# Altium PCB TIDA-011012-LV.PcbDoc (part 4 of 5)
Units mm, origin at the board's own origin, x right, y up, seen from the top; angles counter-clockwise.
Board outline 250 x 280 mm, 4 copper layers (Top Layer, Layer 1, Layer 2, Bottom Layer), stack 2.208 mm thick; 410 components, 230 nets, 1280 pads, 1868 vias.
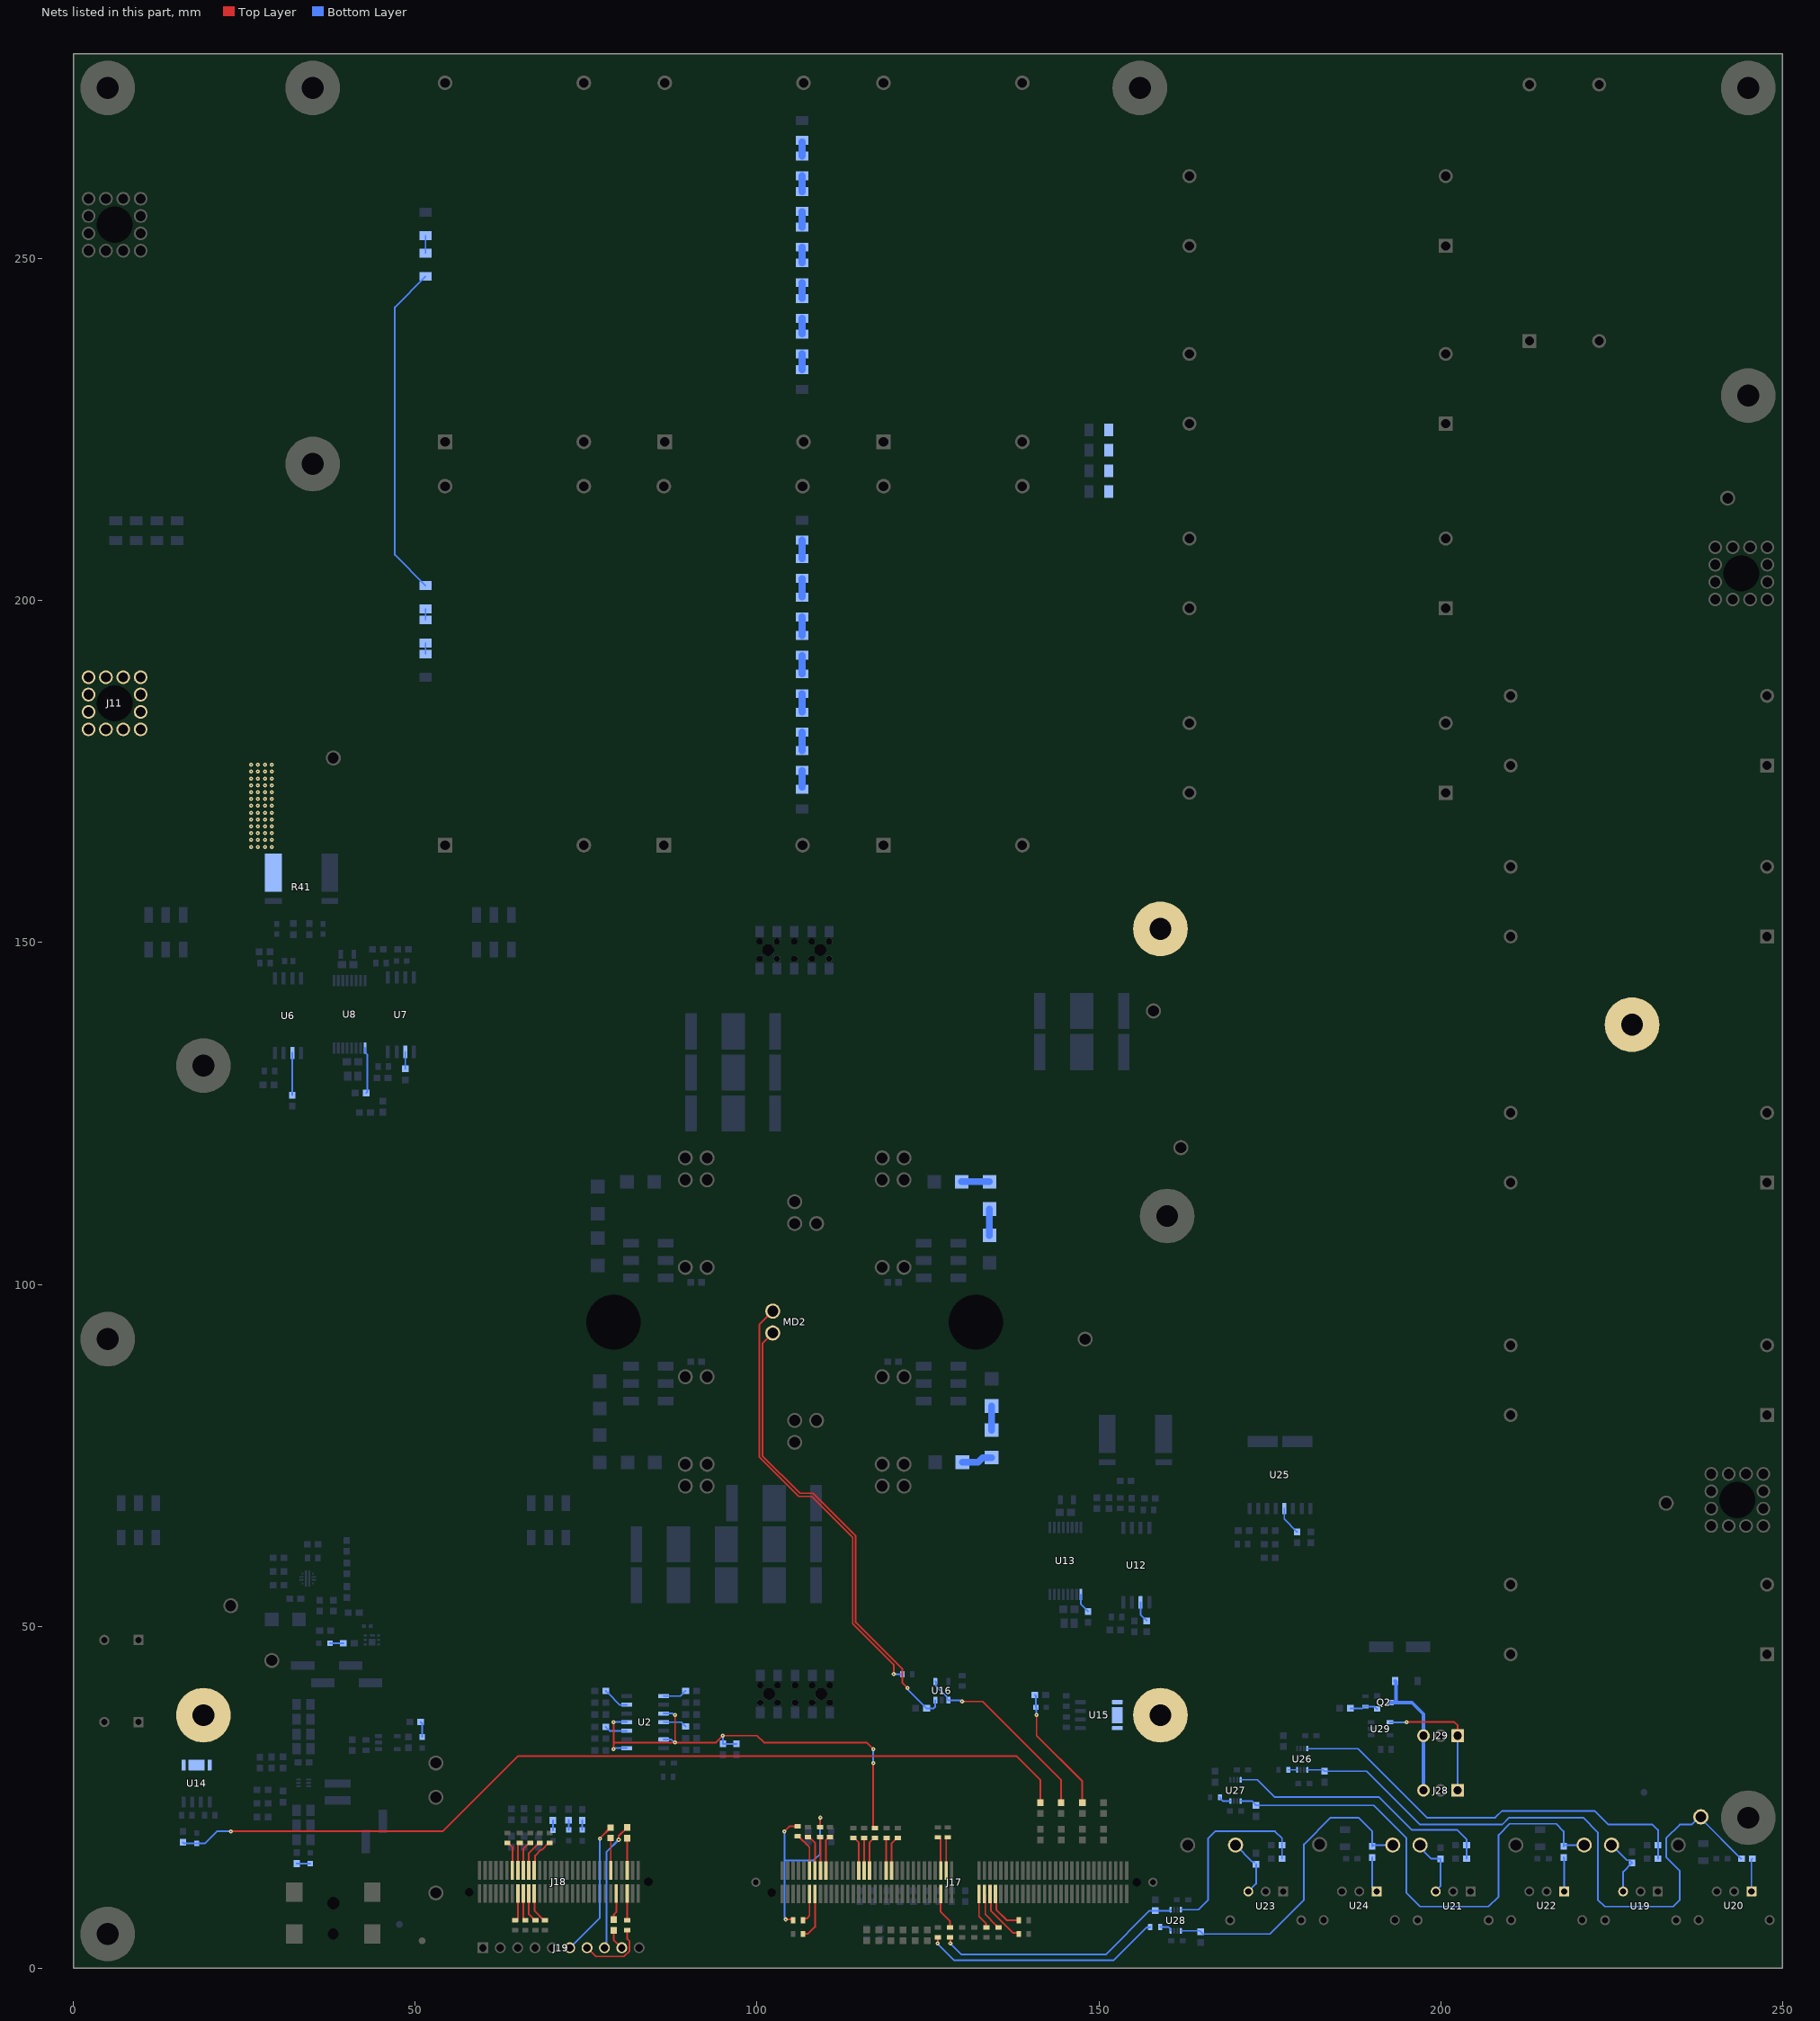
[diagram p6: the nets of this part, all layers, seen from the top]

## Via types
v1: diameter 0.6, hole 0.2, Top Layer to Bottom Layer, tented both sides, 1862 vias
v2: diameter 0.61, hole 0.203, Top Layer to Bottom Layer, tented both sides, 6 vias

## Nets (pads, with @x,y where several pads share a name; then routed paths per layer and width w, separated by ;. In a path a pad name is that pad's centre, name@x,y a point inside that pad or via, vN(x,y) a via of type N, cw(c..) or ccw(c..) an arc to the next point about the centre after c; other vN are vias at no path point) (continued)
NetD15_2: D15.2 D19.1 | length 4.5
  Bottom Layer w1: D15.2@130.043,74 132.323,74 133,74.677 D19.1@134.3,74.677
NetD16_2: D16.2 D20.1 | length 4.1
  Bottom Layer w1: D16.2@129.943,115.023 D20.1@134,115.023
NetD19_2: D19.2 D23.1 | length 3.5
  Bottom Layer w1: D19.2@134.3,78.677 D23.1@134.3,82.214
NetD20_2: D20.2 D24.1 | length 3.9
  Bottom Layer w1: D24.1@134,107.16 D20.2@134,111.023
NetD25_2: D25.2 R49.1 | length 1.5
  Bottom Layer w0.254: R49.1@70.111,21.606 70.163,21.554 D25.2@70.163,20.152
NetD26_2: D26.2 R48.1 | length 1.4
  Bottom Layer w0.254: R48.1@72.427,21.647 72.427,20.244 D26.2@72.428,20.243
NetD27_2: D27.2 R50.1 | length 1.4
  Bottom Layer w0.254: R50.1@74.411,21.605 74.411,20.209 D27.2@74.412,20.207
NetD29_1: D29.1 R140.2 | length 2
  Bottom Layer w0.25: D29.1@37.501,47.517 39.455,47.517 R140.2@39.47,47.532
NetD31_1: D31.1 R147.2 | length 2
  Bottom Layer w0.25: R147.2@32.65,15.287 32.652,15.289 D31.1@34.65,15.289
NetD32_1: D32.1 R148.2 | length 2.3
  Bottom Layer w0.25: R148.2@50.8,36 51,35.8 D32.1@51,33.8
NetD33_2: D33.2 J28.3 J29.3 Q2.3 | length 19.9
  Bottom Layer w0.5: Q2.3@192.704,38.85 193.48,38.85 ; D33.2@193.363,42 193.48,41.882 193.48,38.85 ; J28.3@197.5,26 J29.3@197.5,34 197.5,37.167 195.817,38.85 193.48,38.85
NetH1_1: H1.1 H16.1 R211.1 R212.1 R213.1 R214.1
NetH13_1: H13.1 U14.5 U14.6 U14.7
NetH14_1: H14.1 U15.5 U15.6 U15.7
NetJ11_1: J11.1 R41.1
  other v1: 25.991,164 26.991,164 27.991,164 28.991,164 25.991,165 26.991,165 27.991,165 28.991,165 25.991,166 26.991,166 27.991,166 28.991,166 25.991,167 26.991,167 27.991,167 28.991,167 25.991,168 26.991,168 27.991,168 28.991,168 25.991,169 26.991,169 27.991,169 28.991,169 25.991,170 26.991,170 27.991,170 28.991,170 25.991,171 26.991,171 27.991,171 28.991,171 25.991,172 26.991,172 27.991,172 28.991,172 25.991,173 26.991,173 27.991,173 28.991,173 25.991,174 26.991,174 27.991,174 28.991,174 25.991,175 26.991,175 27.991,175 28.991,175 25.991,176 26.991,176 27.991,176 28.991,176
NetJ17_50: J17.50 R59.1 | length 6.3
  Top Layer w0.254: J17.50@134.867,10.862 134.99,10.739 134.99,8.545 136.534,7 R59.1@138.275,7
NetJ17_52: J17.52 R61.1 | length 8
  Top Layer w0.254: J17.52@134.067,10.862 134.19,10.739 134.19,8.39 137.405,5.175 138.1,5.175 R61.1@138.275,5
NetJ17_54: J17.54 R63.1 | length 5.8
  Top Layer w0.254: J17.54@133.267,10.862 133.39,10.739 133.39,7.871 134.992,6.269 134.992,6.144 135.19,5.946 R63.1@135.315,5.946
NetJ17_56: J17.56 R66.1 | length 5.4
  Top Layer w0.254: J17.56@132.467,10.862 132.467,7.533 133.497,6.503 133.497,5.988 R66.1@133.539,5.946
NetJ17_59: J17.59 R70.2 | length 5
  Top Layer w0.254: J17.59@127.667,14.262 127.667,18.935 127.865,19.133 R70.2@127.888,19.133
NetJ17_61: J17.61 R72.2 | length 5.1
  Top Layer w0.254: R72.2@126.444,19.133 126.569,19.133 126.867,18.835 J17.61@126.867,14.262
NetJ17_62: J17.62 R73.1 | length 5.5
  Top Layer w0.254: J17.62@126.867,10.862 126.867,8.238 128.212,6.893 R73.1@128.212,5.946
NetJ17_79: J17.79 R82.2 | length 5.2
  Top Layer w0.254: J17.79@119.667,14.262 119.667,18.242 120.469,19.044 R82.2@120.594,19.044
NetJ17_81: J17.81 R83.2 | length 4.8
  Top Layer w0.254: J17.81@118.867,14.262 118.867,18.963 R83.2@118.948,19.044
NetJ17_87: J17.87 R87.2 | length 5.2
  Top Layer w0.254: J17.87@116.467,14.262 116.467,18.383 117.128,19.044 R87.2@117.253,19.044
NetJ17_89: J17.89 R88.2 | length 4.8
  Top Layer w0.254: R88.2@115.651,19.044 115.667,19.028 J17.89@115.667,14.262
NetJ17_91: J17.91 R90.2 | length 5.2
  Top Layer w0.254: R90.2@114.092,19.044 114.217,19.044 114.867,18.395 J17.91@114.867,14.262
NetJ17_103: J17.103 R100.2 | length 5.3
  Top Layer w0.254: J17.103@110.067,14.262 110.067,18.707 110.554,19.194 R100.2@110.679,19.194
NetJ17_105: J17.105 R102.2 | length 4.9
  Top Layer w0.254: R102.2@109.237,19.194 109.267,19.165 J17.105@109.267,14.262
NetJ17_107: J17.107 R105.2 | length 5.4
  Top Layer w0.254: R105.2@107.463,19.194 107.588,19.194 108.467,18.315 J17.107@108.467,14.262
NetJ17_108: J17.108 R106.2 | length 7
  Top Layer w0.254: R106.2@106.725,5 107.431,5 108.467,6.036 J17.108@108.467,10.862
NetJ17_109: J17.109 R107.2 | length 5.8
  Top Layer w0.254: R107.2@105.934,19.275 106.059,19.275 107.667,17.667 J17.109@107.667,14.262
NetJ17_110: J17.110 R108.2 | length 4.4
  Top Layer w0.254: R108.2@106.725,7 106.725,7.053 106.923,7.251 107.251,7.251 107.667,7.667 J17.110@107.667,10.862
NetJ18_125: J18.125 R115.2 | length 4.7
  Top Layer w0.254: J18.125@80.999,14.306 80.999,18.999 R115.2@81,19
NetJ18_126: J18.126 R116.2 | length 3.9
  Top Layer w0.254: J18.126@80.999,10.906 80.999,7.001 R116.2@81,7
NetJ18_130: J18.130 R118.1 | length 3.9
  Top Layer w0.254: R118.1@79.024,7.113 79.033,7.123 79.033,7.846 79.399,8.211 J18.130@79.399,10.906
NetJ18_131: J18.131 R119.1 | length 4.8
  Top Layer w0.254: R119.1@78.568,19.049 78.599,19.019 J18.131@78.599,14.306
NetJ18_159: J18.159 R125.1 | length 5.1
  Top Layer w0.254: J18.159@67.399,14.306 67.522,14.429 67.522,16.465 68.35,17.294 68.504,17.294 69.531,18.32 R125.1@69.656,18.32
NetJ18_160: J18.160 R126.2 | length 4.7
  Top Layer w0.254: J18.160@67.522,10.975 67.426,10.879 67.426,8.401 68.827,7 R126.2@68.952,7
NetJ18_161: J18.161 R127.1 | length 4.7
  Top Layer w0.254: J18.161@66.599,14.306 66.599,16.827 68.076,18.305 R127.1@68.201,18.305
NetJ18_162: J18.162 R128.2 | length 4.4
  Top Layer w0.254: J18.162@66.599,10.906 66.599,7.875 67.474,7 R128.2@67.599,7
NetJ18_163: J18.163 R129.1 | length 4.5
  Top Layer w0.254: J18.163@65.799,14.306 65.799,17.419 66.704,18.324 R129.1@66.829,18.324
NetJ18_164: J18.164 R130.2 | length 4.1
  Top Layer w0.254: J18.164@65.799,10.906 65.799,7.198 65.997,7 R130.2@66.096,7
NetJ18_165: J18.165 R131.1 | length 4.2
  Top Layer w0.254: J18.165@64.999,14.306 64.999,18.126 65.197,18.324 R131.1@65.294,18.324
NetJ18_166: J18.166 R132.2 | length 4.1
  Top Layer w0.254: R132.2@64.599,7 64.724,7 64.999,7.275 J18.166@64.999,10.906
NetJ18_167: J18.167 R133.1 | length 4.4
  Top Layer w0.254: R133.1@63.466,18.326 63.591,18.326 64.199,17.718 J18.167@64.199,14.306
NetJ28_1: J28.1 J29.1 U29.4 | length 19.6
  Top Layer w0.25: v1(195,36) 202,36 202.5,35.5 J29.1@202.5,34
  Bottom Layer w0.25: U29.4@192.574,35.964 194.964,35.964 v1(195,36) ; J28.1@202.5,26 J29.1@202.5,34
NetQ2_1: Q2.1 R187.2 R188.2 | length 4.2
  Bottom Layer w0.25: R187.2@186.8,38 188.55,38 188.8,38.25 R188.2@189,38.25 190.304,38.25 190.654,37.9 Q2.1@190.704,37.9
NetR3_1: R3.1 R7.2 | length 2.3
  Bottom Layer w0.5: R3.1@106.592,267.1 R3.1@106.592,267.35
  Bottom Layer w1: R7.2@106.592,265.043 R3.1@106.592,267.1
NetR4_1: R4.1 R15.1 | length 2.3
  Bottom Layer w1: R4.1@106.592,249.421 R15.1@106.592,251.729
NetR4_2: R4.2 R8.1 | length 2.3
  Bottom Layer w1: R8.1@106.592,244.214 R4.2@106.592,246.521
NetR7_1: R7.1 R11.2 | length 2.3
  Bottom Layer w1: R11.2@106.592,259.836 R7.1@106.592,262.143
NetR8_2: R8.2 R12.1 | length 2.3
  Bottom Layer w1: R12.1@106.592,239.007 R8.2@106.592,241.314
NetR11_1: R11.1 R15.2 | length 2.3
  Bottom Layer w1: R15.2@106.592,254.629 R11.1@106.592,256.936
NetR12_2: R12.2 R16.1 | length 2.3
  Bottom Layer w1: R16.1@106.592,233.8 R12.2@106.592,236.107
NetR22_2: R22.2 R28.1 | length 2.7
  Bottom Layer w1: R28.1@106.592,206.153 R22.2@106.592,208.87
NetR24_1: R24.1 R32.2 | length 2.7
  Bottom Layer w1: R32.2@106.592,183.684 R24.1@106.592,186.401
NetR24_2: R24.2 R38.2 | length 2.7
  Bottom Layer w1: R24.2@106.592,189.301 R38.2@106.592,192.019
NetR28_2: R28.2 R34.1 | length 2.7
  Bottom Layer w1: R34.1@106.592,200.536 R28.2@106.592,203.253
NetR32_1: R32.1 R36.2 | length 2.7
  Bottom Layer w1: R36.2@106.592,178.067 R32.1@106.592,180.784
NetR34_2: R34.2 R38.1 | length 2.7
  Bottom Layer w1: R38.1@106.592,194.919 R34.2@106.592,197.636
NetR36_1: R36.1 R40.2 | length 2.7
  Bottom Layer w0.5: R40.2@106.592,172.45 R40.2@106.592,172.7
  Bottom Layer w1: R40.2@106.592,172.7 R36.1@106.592,175.167
NetR111_1: R111.1 U2.3 | length 3.3
  Bottom Layer w0.25: R111.1@77.863,35.28 77.888,35.28 78.456,34.711 U2.3@80.925,34.711
NetR112_1: R112.1 U2.6 | length 3.9
  Bottom Layer w0.25: R112.1@77.863,40.536 77.888,40.536 78.238,40.186 78.238,40.161 79.878,38.521 U2.6@80.925,38.521
NetR114_1: R114.1 U2.8 | length 3.5
  Bottom Layer w0.25: U2.8@86.325,39.791 88.767,39.791 89.525,40.549 R114.1@89.55,40.549
NetR117_1: R117.1 U2.11 | length 3.5
  Bottom Layer w0.25: U2.11@86.325,35.981 88.9,35.981 89.525,35.356 R117.1@89.55,35.356
NetR153_1: R153.1 U6.6 | length 6.2
  Bottom Layer w0.25: U6.6@32.001,133.863 32.001,127.682 R153.1@32.008,127.675
NetR158_2: R158.2 R159.1 | length 2.6
  Bottom Layer w0.254: R159.1@51.5,250.839 R158.2@51.5,253.409
NetR159_2: R159.2 R160.1 | length 49
  Bottom Layer w0.254: R160.1@51.5,202.2 47,206.7 47,242.939 R159.2@51.5,247.439
NetR160_2: R160.2 R161.1 | length 1.6
  Bottom Layer w0.254: R161.1@51.5,197.2 R160.2@51.5,198.8
NetR161_2: R161.2 R162.1 | length 1.6
  Bottom Layer w0.254: R162.1@51.5,192.2 R161.2@51.5,193.8
NetR163_1: R163.1 U7.6 | length 2.5
  Bottom Layer w0.25: R163.1@48.536,131.528 U7.6@48.536,134.013
NetR165_1: R165.1 U8.1 | length 6.8
  Bottom Layer w0.25: U8.1@42.641,134.588 42.641,133.968 43,133.609 43,128.2 R165.1@42.8,128
NetR183_1: R183.1 U12.6 | length 3.1
  Bottom Layer w0.25: U12.6@156.1,53.5 156.1,51.725 157,50.825 R183.1@157,50.8
NetR185_1: R185.1 U13.1 | length 2.9
  Bottom Layer w0.25: U13.1@147.39,54.632 147.39,53.217 148.416,52.191 R185.1@148.416,52.166
NetR194_2: R194.2 TP4.1 U19.3 | length 8.8
  Bottom Layer w0.25: TP4.1@225,18 227.225,15.775 227.65,15.775 228,15.425 R194.2@228,15.4 228,15.375 226.708,14.083 U19.3@226.708,11.201
NetR195_1: R195.1 U20.1 | length 4.8
  Bottom Layer w0.25: U20.1@245.479,11.226 245.479,15.879 R195.1@245.6,16
NetR197_2: R197.2 TP7.1 U21.3 | length 9.1
  Bottom Layer w0.25: TP7.1@197,18 197,17.633 198.633,16 R197.2@200,16 200,12.046 199.289,11.336 U21.3@199.289,11.201
NetR198_1: R198.1 U22.1 | length 5
  Bottom Layer w0.25: R198.1@218,16.2 218.06,16.14 U22.1@218.06,11.226
NetR199_1: R199.1 U25.6 | length 4.2
  Bottom Layer w0.25: U25.6@177.135,67.247 177.135,65.69 179,63.825 R199.1@179,63.8
NetR209_2: R209.2 TP10.1 U23.3 | length 8.3
  Bottom Layer w0.25: TP10.1@170,18 172.425,15.575 172.65,15.575 R209.2@172.775,15.45 ; U23.3@171.871,11.201 173,12.331 R209.2@173,15.2
NetR210_1: R210.1 U24.1 | length 5.2
  Bottom Layer w0.25: R210.1@190,16.2 190,11.867 U24.1@190.641,11.226
NetR215_2: R215.2 U26.4 | length 1.3
  Bottom Layer w0.25: R215.2@177.725,29 U26.4@179,29
NetR216_2: R216.2 U27.4 | length 1.8
  Bottom Layer w0.25: R216.2@167.725,25 167.725,24.875 168.15,24.45 U27.4@169.25,24.45
NetR217_2: R217.2 U28.4 | length 1.9
  Bottom Layer w0.25: R217.2@158.975,6 160.2,6 160.5,5.7 U28.4@160.5,5.45
NTC1_N: MD2.T2 R190.2 U16.3 | length 68.9
  Top Layer w0.25: MD2.T2@102.3,92.9 100.775,91.375 100.775,74.943 106.268,69.45 108.186,69.45 114.438,63.198 114.438,50.562 121.273,43.727 121.273,41.727 v1(122,41)
  Bottom Layer w0.25: v1(122,41) 122.067,40.933 122.067,40.708 R190.2@124.775,38 ; R190.2@124.8,38 125.854,38 126.05,38.196 126.05,39.157 U16.3@126.07,39.177
NTC1_P: MD2.T1 R218.1 | length 64.5
  Top Layer w0.25: MD2.T1@102.3,96.1 100.325,94.125 100.325,74.756 106.081,69 108,69 113.988,63.012 113.988,50.375 120,44.364 v1(120,43)
  Bottom Layer w0.25: v1(120,43) R218.1@121.275,43
PWM_BUF_EN: C53.2 R87.1 R205.2 U2.1 U2.4 U2.10 U2.13 | length 69.7
  Top Layer w0.25: v1(79,32) 79,32.939 ; v1(79,36) 79,32.939 ; v1(88,37) v1(88,33) ; v1(117,30) 117,20.694 117.2,20.494 R87.1@117.253,20.494 ; v1(117,32) 116,33 101,33 100,34 v1(95,34) 94,33 v1(88,33) ; 79,32.939 79.061,33 v1(88,33)
  Bottom Layer w0.25: v1(79,32) 79.097,32 79.264,32.167 80.921,32.167 U2.1@80.925,32.171 ; v1(79,36) 79.01,35.99 80.916,35.99 U2.4@80.925,35.981 ; U2.13@86.325,33.441 87.48,33.441 87.921,33 v1(88,33) ; U2.10@86.325,37.251 87.652,37.251 87.903,37 v1(88,37) ; v1(95,34) C53.2@95,32.8 R205.2@97,32.8 ; v1(117,30) v1(117,32)
PWM_CLK_SD_DC_DELAYED: R102.1 R107.1 R108.1 | length 28.6
  Top Layer w0.25: v1(104,20) 104.725,20.725 R107.1@105.934,20.725 ; v1(104.212,7.129) 105.146,7.129 R108.1@105.275,7 ; R102.1@109.237,20.644 v1(109.237,22)
  Bottom Layer w0.25: v1(104,20) 104,15.734 ; v1(104.212,7.129) 104.212,7.224 104,7.436 104,15.734 ; v1(109.237,22) 109.237,16.713 108.291,15.767 104.033,15.767 104,15.734
PWM_SYNC_RX: R74.2 R217.1 | length 35
  Top Layer w0.25: v1(126.436,3.603) R74.2@126.436,4.496
  Bottom Layer w0.25: v1(126.436,3.603) 126.436,3.564 128.859,1.141 152.141,1.141 156.971,5.971 157.496,5.971 R217.1@157.525,6
PWM_SYNC_TX: C151.1 R73.2 U28.5 | length 36.6
  Top Layer w0.25: R73.2@128.212,4.496 128.288,4.419 v1(128.288,3.603)
  Bottom Layer w0.25: v1(128.288,3.603) 129.891,2 151,2 157.4,8.4 C151.1@158.25,8.4 160.475,8.4 160.5,8.425 U28.5@160.5,8.55
RXCLK_5V: C148.1 R195.2 TP6.1 U26.1 | length 94.5
  Bottom Layer w0.25: U26.1@180.5,29 182.8,29 C148.1@183,28.8 189.2,28.8 197,21 209,21 210,22 220.854,22 223,19.854 223,10 224,9 234,9 235,10 235,14.227 233,16.227 233,19 235,21 236.725,21 237.627,21.902 TP6.1@238.073,21.902 ; TP6.1@238.073,22.128 TP6.1@238.073,21.902 ; R195.2@244,16 243.975,16 TP6.1@238.073,21.902
RXD0_5V: C150.1 R198.2 TP9.1 U27.1 | length 74.4
  Bottom Layer w0.25: U27.1@170.75,24.45 172.375,24.45 173,23.825 C150.1@173,23.8 190.2,23.8 195,19 195,11 197,9 207,9 208.479,10.479 208.479,19.479 210.105,21.105 216.895,21.105 218,20 R198.2@218,17.8 218.2,18 TP9.1@221,18
RXD1_5V: C152.1 R210.2 TP12.1 U28.1 | length 46.1
  Bottom Layer w0.25: U28.1@162,5.45 164.762,5.45 165.212,5 175,5 180,10 180,18.114 183.886,22 188,22 190,20 R210.2@190,17.8 190.2,18 TP12.1@193,18
SPIB_CLK: J19.9 R118.2 | length 3
  Top Layer w0.254: R118.2@79.024,5.513 79.024,4.162 J19.9@80.209,2.976
SPIB_PICO: J19.8 R115.1 | length 19
  Top Layer w0.254: v1(79.749,18.774) 79.749,19.324 81,20.575 R115.1@81,20.6
  Bottom Layer w0.254: J19.8@77.669,2.976 77.927,3.234 77.927,3.725 78,3.798 78,17.025 v1(79.749,18.774)
SPIB_POCI: J19.7 R116.1 | length 10.2
  Top Layer w0.254: J19.7@75.129,2.976 76.399,1.706 80.533,1.706 81.336,2.51 81.336,3.924 81,4.26 R116.1@81,5.55
SPIB_PTE: J19.6 R119.2 | length 20.1
  Top Layer w0.254: v1(76.999,18.925) 76.999,18.984 78.566,20.551 R119.2@78.568,20.551
  Bottom Layer w0.254: J19.6@72.589,2.976 76.999,7.386 v1(76.999,18.925)
TEMP1: C124.2 R85.1 R186.1 | length 135.6
  Top Layer w0.25: v2(23,20) 54,20 65,31 138,31 141.438,27.562 R85.1@141.438,24.209
  Bottom Layer w0.25: R186.1@16,18.4 16.15,18.25 C124.2@18,18.25 19.25,18.25 21,20 v2(23,20)
TEMP2: C127.2 R56.1 R189.1 | length 18.6
  Top Layer w0.254: v1(140.892,37) 140.892,34.021 147.588,27.324 R56.1@147.588,24.209
  Bottom Layer w0.254: R189.1@140.642,39.957 140.815,39.783 C127.2@140.815,38.157 140.853,38.119 140.853,37.038 v1(140.892,37)
TEMP3: R77.1 U16.1 U16.4 | length 28.2
  Top Layer w0.254: v1(130,39) 133,39 144.488,27.512 R77.1@144.488,24.209
  Bottom Layer w0.254: U16.4@126.07,41.927 126.187,41.811 126.187,41.243 127.797,39.633 127.797,39.35 U16.1@127.97,39.177 129.823,39.177 v1(130,39)
TXCLK_5V: C134.2 R193.1 U26.8 | length 61.3
  Bottom Layer w0.25: U26.8@180.5,32.1 187.894,32.1 197.994,22 208,22 209,23 222.53,23 224.53,21 231,21 231.8,20.2 R193.1@231.8,18 C134.2@231.8,16
TXD0_5V: C136.2 R196.1 U27.8 | length 39.5
  Bottom Layer w0.25: U27.8@170.75,27.55 173.183,27.55 175.733,25 191,25 195.78,20.22 202.43,20.22 203.8,18.85 C136.2@203.8,18 R196.1@203.8,16
TXD1_5V: C139.2 R208.1 U28.8 | length 28.2
  Bottom Layer w0.25: U28.8@162,8.55 164.55,8.55 166,10 166,19 167,20 175.775,20 176.8,18.975 C139.2@176.8,18 R208.1@176.8,16
pads on no net: FID1.1 FID2.1 FID3.1 H2.1 H3.1 H4.1 H5.1 H6.1 H7.1 H8.1 H9.1 H10.1 H12.1 J5. J6. J11. J12. J15. J16. J17.1 J17.2 J17.3 J17.4 J17.5 J17.6 J17.8 J17.11 J17.12 J17.14 J17.17 J17.18 J17.20 J17.23 J17.24 J17.26 J17.27 J17.28 J17.29 J17.30 J17.31 J17.32 J17.33 J17.34 J17.36 J17.37 J17.39 J17.40 J17.41 J17.42 J17.43 J17.44 J17.45 J17.49 J17.51 J17.53 J17.55 J17.57 J17.63 J17.66 J17.67 J17.69 J17.71 J17.73 J17.75 J17.77 J17.80 J17.82 J17.85 J17.86 J17.88 J17.90 J17.92 J17.93 J17.94 J17.95 J17.96 J17.99 J17.100 J17.101 J17.102 J17.104 J17.106 J17.113 J17.114 J17.115 J17.116 J17.117 J17.118 J17.119 J17.120 J17.181 J17.182 J17.185 J17.186 J18.61 J18.62 J18.121 J18.122 J18.123 J18.124 J18.127 J18.128 J18.129 J18.132 J18.133 J18.134 J18.136 J18.137 J18.138 J18.139 J18.140 J18.141 J18.142 J18.143 J18.144 J18.145 J18.146 J18.147 J18.148 J18.149 J18.150 J18.151 J18.152 J18.153 J18.154 J18.155 J18.156 J18.168 J18.169 J18.170 J18.171 J18.172 J18.173 J18.174 J18.175 J18.176 J18.177 J18.178 J21.MH1 J21.MH2 LBL1.0 MD2. Q1.0 U14.2 U15.2 U19.1 U19.4 U19.5 U20.4 U20.5 U21.1 U21.4 U21.5 U22.4 U22.5 U23.1 U23.4 U23.5 U24.4 U24.5 U25.4 U25.5 U29.1

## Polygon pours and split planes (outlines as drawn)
NetC1_2 on Bottom Layer "BOTTOM_LAYER_NETC1_2_P454" (solid, remove dead copper, pour order 454): 142,124 142,117 165,117 165,124
DC_DAB on Bottom Layer "Top Layer-DC_BUS_DAB" (solid, remove dead copper, pour order 307): 56,157 56,146 65,146 66,147 66,160 109,160 115,154 115,144 110,139 102,139 102,122 101,121 101,104 102,103 107,98 107,91 100,84 100,78 103,75 108,75 108,53 115,53 115,65 113,67 113,77 116,80 116,111 113,114 113,121 117,125 136,125 142,131 142,148 144,150 144,208 113,208 113,169.55 100,169.55 100,208 64,208 64,190 53,179 53,160
NetC11_1 on Bottom Layer "BOTTOM_LAYER_NETC11_1_P453" (solid, remove dead copper, pour order 453): 146,131 149,131 149,137 146,137
NetC23_1 on Bottom Layer "BOTTOM_LAYER_NETC23_1_P452" (solid, remove dead copper, pour order 452): 146,137 149,137 149,143 146,143
GND on Bottom Layer "BOTTOM_LAYER_GND_P449" (solid, remove dead copper, pour order 449): 105.992,143.95 106,143.942 106,142 108,142 111,145 111,154 109,156 107,156 107,154 108,153 108,146 107,145 106,145 106,144
NetC2_1 on Bottom Layer "BOTTOM_LAYER_NETC2_1_P447" (solid, remove dead copper, pour order 447): 249,147 249,188 243,188 243,147
I_HALL_P on Bottom Layer "BOTTOM_LAYER_I_HALL_P_P446" (solid, remove dead copper, pour order 446): 207,147 207,188 217,188 217,147
NetH1_1 on Bottom Layer "BOTTOM_LAYER_NETH1_1_P444" (solid, remove dead copper, pour order 444): 220,142 222,144 230,144 232,142 234,140 234,136 231,133 225,133 220,138 198,138 188,148 155,148 153,150 153,213 151,215 151,227 153,227 155,225 155,163 164,154 188,154 200,142
NetC1_1 on Bottom Layer "BOTTOM_LAYER_NETC1_1_P441" (solid, remove dead copper, pour order 441): 203,168 190,168 190,267.1 204,267.1 204,251 214.9,240.1 226.907,240.1 250,217 250,197 207,197 203,193
GND on Bottom Layer "BOTTOM_LAYER_GND_P436" (solid, remove dead copper, pour order 436): 0,97 8,97 10,95 10,89 8,87 0,87 0,0 63.591,0 64.102,0.512 249,0.512 249,27 199.854,27 199.854,62.971 194.503,68.322 171.667,68.322 171.667,67.526 158.774,54.632 141,54.632 141,53 132.052,44.052 65,44.052 65,53 51.354,66.646 23.176,66.646 20.432,69.39 20.432,122 45,122 52,129 52,136 11,136 0,125
NetH14_1 on Bottom Layer "BOTTOM_LAYER_NETH14_1_P435" (solid, remove dead copper, pour order 435): 152,39.001 154.999,42 162,42 164,40 164,34 162,32 155,32 152,35
NetH13_1 on Bottom Layer "BOTTOM_LAYER_NETH13_1_P434" (solid, remove dead copper, pour order 434): 16,29 20,29 22,31 22,32 24,34 24,40 22,42 16,42 14,40 14,31
GND on Bottom Layer "BOTTOM_LAYER_GND_P433" (solid, remove dead copper, pour order 433): 6,65 14,65 14,60 6,60
12V on Bottom Layer "BOTTOM_LAYER_12V_P427" (solid, remove dead copper, pour order 427): 41,40 47,40 47,43 41,43
GND on Bottom Layer "BOTTOM_LAYER_GND_P426" (solid, remove dead copper, pour order 426): 145.612,55.757 145.612,49.892 144.765,49.044 140.749,49.044 140.749,54.629 141.855,55.735
5V on Bottom Layer "BOTTOM_LAYER_5V_P425" (solid, remove dead copper, pour order 425): 145.793,49.794 145.755,49.831 145.755,55.757 147.067,55.757 147.073,55.751 147.073,49.798
5V_ISO_SN_SENS on Bottom Layer "BOTTOM_LAYER_5V_ISO_SN_SENS_P424" (solid, remove dead copper, pour order 424): 144.84,63.644 144.84,69.178 144.178,69.178 142.479,67.479 142.479,64.731 142.23,64.482 142.249,64.463 142.249,63.644
I_SW_NEG on Bottom Layer "BOTTOM_LAYER_I_SW_NEG_P423" (solid, remove dead copper, pour order 423): 144.749,63.744 144.749,65.444 145.44,66.135 145.44,69.144 149,69.144 149,63.744
GND on Bottom Layer "BOTTOM_LAYER_GND_P422" (solid, remove dead copper, pour order 422): 40.863,135.713 40.863,129.847 40.016,129 36,129 36,134.584 37.106,135.691
5V on Bottom Layer "BOTTOM_LAYER_5V_P421" (solid, remove dead copper, pour order 421): 41.043,129.75 41.006,129.787 41.006,135.713 42.318,135.713 42.324,135.707 42.324,129.754
NetC22_1 on Bottom Layer "BOTTOM_LAYER_NETC22_1_P420" (solid, remove dead copper, pour order 420): 46,32.443 46,29 42,29 39.963,31.037 39.963,32.443
3V3 on Bottom Layer "BOTTOM_LAYER_3V3_P419" (solid, remove dead copper, pour order 419): 47,33 47,28 55,28 55,33
NetC70_1 on Bottom Layer "BOTTOM_LAYER_NETC70_1_P406" (solid, remove dead copper, pour order 406): 34.04,40 34.04,43 39,43 39,40 36.563,40 36.563,29.331 34.685,27.453 34,27.453 34,29
NetC58_2 on Bottom Layer "BOTTOM_LAYER_NETC58_2_P413" (solid, remove dead copper, pour order 413): 34.048,26.932 34.048,27.271 34.072,27.295 34.859,27.295 35.651,28.087 40.65,28.087 40.65,26.087 35.65,26.087 34.807,26.931 34.047,26.931
5V on Bottom Layer "BOTTOM_LAYER_5V_P414" (solid, remove dead copper, pour order 414): 43.387,25.087 34.65,25.087 33.65,24.087 33.65,16.087 43.387,16.087
GND on Bottom Layer "BOTTOM_LAYER_GND_P415" (solid, remove dead copper, pour order 415): 33.395,16.076 33.384,16.087 30.65,16.087 30.65,24.087 33.373,26.81 33.373,28.195 30.65,30.917 30.65,39.087 33.275,39.087 33.291,39.103 33.373,39.022 33.373,29.071 33.989,28.455 33.989,26.769 34.724,26.769 35.155,26.338 35.155,25.804 34.442,25.091 33.803,24.452 33.373,24.022
12V_FET_DRAIN on Bottom Layer "BOTTOM_LAYER_12V_FET_DRAIN_P418" (solid, remove dead copper, pour order 418): 40.54,47.016 40.54,48.291 45,48.291 45,47.011
12V_OUT on Bottom Layer "BOTTOM_LAYER_12V_OUT_P417" (solid, remove dead copper, pour order 417): 34.148,57.115 33.865,57.115 33.865,55.748 32,53.883 32,43.662 36.475,43.662 36.475,52.525 34.148,54.852
12V_IN on Bottom Layer "BOTTOM_LAYER_12V_IN_P416" (solid, remove dead copper, pour order 416): 34.352,56.885 34.635,56.885 34.635,58.252 35,58.617 35,64 33,64 33,59.588 34.352,58.236
NetC1_2 on Bottom Layer "BOTTOM_LAYER_NETC1_2_P405" (solid, remove dead copper, pour order 405): 161,267 173,279 226,279 229,276 229,273 177,273 170,266 170,168 161,168
NetJ11_1 on Bottom Layer "BOTTOM_LAYER_NETJ11_1_P362" (solid, remove dead copper, pour order 362): 30,158 24,158 4,178 0,178 0,192 30,192
GND on Bottom Layer "BOTTOM_LAYER_GND_P401" (solid, remove dead copper, pour order 401): 4,209 4,205 18,205 18,209
NetC7_1 on Bottom Layer "BOTTOM_LAYER_NETC7_1_P400" (solid, remove dead copper, pour order 400): 4,216 4,211 18,211 18,216
NetC7_1 on Bottom Layer "Bottom Layer-NetC7_1" (solid, remove dead copper, pour order 397): 149,214 149,227 51,227 51,214
5V_ISO_DC_SENS on Bottom Layer "BOTTOM_LAYER_5V_ISO_DC_SENS_P386" (solid, remove dead copper, pour order 386): 39.6,143.6 39.6,149.134 37.729,149.134 37.729,144.687 37.481,144.438 37.5,144.419 37.5,143.6
DC_DAB on Bottom Layer "BOTTOM_LAYER_DC_DAB_P385" (solid, remove dead copper, pour order 385): 40,143.7 40,145.4 40.691,146.091 40.691,149.1 44.3,149.1 44.3,143.7
NetD15_1 on Bottom Layer "BOTTOM_LAYER_NETD15_1_P383" (solid, remove dead copper, pour order 383): 140,68 140,67 136,63 122,63 117,68 117,75 124,75 124,70 137,70 140,73 140,79 143,82 143,99 153,99 153,75 149,75 149,73 145,73
DC_POS on Bottom Layer "BOTTOM_LAYER_DC_POS_P381" (solid, remove dead copper, pour order 381): 153,143 153,131 159,131 160,132 160,143 153.65,143
NetC163_1 on Bottom Layer "BOTTOM_LAYER_NETC163_1_P380" (solid, remove dead copper, pour order 380): 95,140 95,135 98,135 98,140
NetC65_1 on Bottom Layer "BOTTOM_LAYER_NETC65_1_P379" (solid, remove dead copper, pour order 379): 95,129 95,134 98,134 98,129
NetC25_1 on Bottom Layer "BOTTOM_LAYER_NETC25_1_P378" (solid, remove dead copper, pour order 378): 95,122 98,122 98,128 95,128
DC_POS on Bottom Layer "BOTTOM_LAYER_DC_POS_P377" (solid, remove dead copper, pour order 377): 91,140 88,140 88,113 94,113 94,120 91,120
NetC2_1 on Bottom Layer "BOTTOM_LAYER_NETC2_1_P373" (solid, remove dead copper, pour order 373): 232,127 232,44 249,44 249,127
I_HALL_P on Bottom Layer "BOTTOM_LAYER_I_HALL_P_P369" (solid, remove dead copper, pour order 369): 193,99 208,114 208,126 217,126 217,44 207,44 207,65 196,76 177,76 177,99
DC_POS on Bottom Layer "BOTTOM_LAYER_DC_POS_P368" (solid, remove dead copper, pour order 368): 114,270.25 140.25,244 154,244 154,265.768 144,275.768 144,276 141,279 50,279 39,268 1,268 1,248 28,248 40,260 88.75,260 99,270.25
DC_DAB on Bottom Layer "BOTTOM_LAYER_DC_DAB_P361" (solid, remove dead copper, pour order 361): 36,158 36,185 47,185 47,158
DC_DAB on Bottom Layer "BOTTOM_LAYER_DC_DAB_P360" (solid, remove dead copper, pour order 360): 78,53 83,53 83,65 78,65
NetC71_1 on Bottom Layer "BOTTOM_LAYER_NETC71_1_P358" (solid, remove dead copper, pour order 358): 101,58 101,53 104,53 104,58
NetC13_1 on Bottom Layer "BOTTOM_LAYER_NETC13_1_P357" (solid, remove dead copper, pour order 357): 101,64 101,60 104,60 104,64
NetC12_1 on Bottom Layer "BOTTOM_LAYER_NETC12_1_P356" (solid, remove dead copper, pour order 356): 101,71 104,71 104,66 101,66
NetC24_1 on Bottom Layer "BOTTOM_LAYER_NETC24_1_P355" (solid, remove dead copper, pour order 355): 87,58 90,58 90,53 87,53
NetC164_1 on Bottom Layer "BOTTOM_LAYER_NETC164_1_P354" (solid, remove dead copper, pour order 354): 87,65 87,60 90,60 90,65
DC_POS on Bottom Layer "BOTTOM_LAYER_DC_POS_P353" (solid, remove dead copper, pour order 353): 94,53 97,53 97,74 96,75 88,75 88,69 89,68 94,68
DC_POS on Bottom Layer "BOTTOM_LAYER_DC_POS_P329" (solid, remove dead copper, pour order 329): 20,147 20,154 15,159 10,159 10,147
I_HALL_N on Bottom Layer "BOTTOM_LAYER_I_HALL_N_P310" (solid, remove dead copper, pour order 310): 158,99 176,99 176,76 158,76
GND on Top Layer "TOP_LAYER_GND_P437" (solid, remove dead copper, pour order 437): 0,97 7,97 10,94 10,89 8,87 0,87 0,0 63.591,0 64.102,0.512 249,0.512 249,27 199.854,27 199.854,62.971 194.503,68.322 171.667,68.322 171.667,67.526 158.774,54.632 141,54.632 141,53 132.052,44.052 65,44.052 65,53 51.354,66.646 23.176,66.646 20.432,69.39 20.432,122 45,122 52,129 52,136 11,136 0,125
DC_DAB on Top Layer "TOP_LAYER_DC_DAB_P450" (solid, remove dead copper, pour order 450): 56,164.919 56,163 54.35,161.35 37.65,161.35 36,163 36,179 42,179 46,175 52,169 52,168.919
DC_POS on Top Layer "Top Layer-DC_POS" (solid, remove dead copper, pour order 364): 149,129 149,144 152,147 152,157 156,161 156,264 142,278 49,278 49,268 0,268 0,230 25,230 28,227 28,199 32,195 10,173 10,155 17,155 17,175 34.5,192.5 42,185 60,167 60,117 51,108 51,75 59,67 62,64 96,64 96,78 84,78 73,89 73,99 85,111 95,111 108,124 115,124 120,129
NetC1_1 on Top Layer "TOP_LAYER_NETC1_1_P439" (solid, remove dead copper, pour order 439): 203,168 190,168 190,267 204,267 204,251 215,240 227,240 233,234 250,217 250,197 237,197 207,197 203,193
NetC1_2 on Top Layer "TOP_LAYER_NETC1_2_P375" (solid, remove dead copper, pour order 375): 167,162 159,170 159,266 170,266 170,174 176,168 176,155 176,118 175,117 131,117 127,113 118,113 117,114 117,120 121,124 160,124 167,131
GND on Top Layer "TOP_LAYER_GND_P408" (solid, remove dead copper, pour order 408): 42,3 42.024,2.976 46.008,2.976 46.008,13 42,13
NetC2_1 on Top Layer "TOP_LAYER_NETC2_1_P371" (solid, remove dead copper, pour order 371): 232,129 236,133 236,142 232,146 232,188 249,188 249,44 232,44
I_HALL_P on Top Layer "TOP_LAYER_I_HALL_P_P370" (solid, remove dead copper, pour order 370): 177,76 177,99 193,99 207.828,113.828 207.828,188 217,188 217,44 207,44 207,65 196,76
DC_DAB on Top Layer "TOP_LAYER_DC_DAB_P332" (solid, remove dead copper, pour order 332): 103,77 103,83 106,86 106,103 102,107 102,112 104,114 107,114 113,108 113,79 109,75 105,75
NetD15_1 on Top Layer "TOP_LAYER_NETD15_1_P344" (solid, remove dead copper, pour order 344): 119,67 122,64 136,64 145,73 153,73 153,99 143,99 143,82 137,76 116,76 116,70
I_HALL_N on Top Layer "TOP_LAYER_I_HALL_N_P347" (solid, remove dead copper, pour order 347): 158,99 176,99 176,76 158,76
DC_DAB on Layer 1 "LAYER_1_DC_DAB_P451" (solid, remove dead copper, pour order 451): 23,143 23,152 25,154 42,154 46,150 59,150 59,143
DC_DAB on Layer 1 "LAYER_1_DC_DAB_P350" (solid, remove dead copper, pour order 350): 43,157 47,153 62,153 63,152 63,136 51,124 51,75 76,50 112,50 115,53 115,124 119,128 150,128 150,145 152,147 152,157 156,161 156,206 36,206 36,157
I_HALL_P on Layer 1 "LAYER_1_I_HALL_P_P432" (solid, remove dead copper, pour order 432): 207,65 196,76 179,76 177,78 177,98 178,99 193,99 208,114 208,188 217,188 217,44 207,44
NetC1_1 on Layer 1 "LAYER_1_NETC1_1_P442" (solid, remove dead copper, pour order 442): 203,168 190,168 190,267 204,267 204,251 215,240 227,240 233,234 250,217 250,197 237,197 207,197 203,193
GND on Layer 1 "LAYER_1_GND_P438" (solid, remove dead copper, pour order 438): 51.354,66.646 23.176,66.646 20.432,69.39 20.432,122 45,122 52,129 52,136 11,136 0,125 0,0 63.591,0 64.102,0.512 249,0.512 249,27 199.854,27 199.854,62.971 194.503,68.322 171.667,68.322 171.667,67.526 158.774,54.632 141,54.632 141,53 132.052,44.052 65,44.052 65,53
NetC1_2 on Layer 1 "LAYER_1_NETC1_2_P393" (solid, remove dead copper, pour order 393): 175,117 176,118 176,168 170,174 170,266 161,266 161,168 167,162 167,131 159,123 120,123 117,120 117,114 118,113 127,113 131,117
NetJ11_1 on Layer 1 "LAYER_1_NETJ11_1_P365" (solid, remove dead copper, pour order 365): 30,163 1,163 1,192 30,192
NetC7_1 on Layer 1 "LAYER_1_NETC7_1_P399" (solid, remove dead copper, pour order 399): 156,213 156,227 53,227 43,237 14,237 6,229 6,212 14,212 14,230 17,233 40,233 47,226 47,213
NetC2_1 on Layer 1 "LAYER_1_NETC2_1_P372" (solid, remove dead copper, pour order 372): 232,129 236,133 236,142 232,146 232,188 249,188 249,44 232,44
DC_POS on Layer 1 "LAYER_1_DC_POS_P367" (solid, remove dead copper, pour order 367): 142,278 156,264 156,233 58.25,233 49.25,242 1,242 1,268 39,268 49,278
NetD15_1 on Layer 1 "LAYER_1_NETD15_1_P338" (solid, remove dead copper, pour order 338): 119,67 122,64 136,64 145,73 153,73 153,99 143,99 143,82 137,76 118,76 116,74 116,69 118,67
I_HALL_N on Layer 1 "LAYER_1_I_HALL_N_P337" (solid, remove dead copper, pour order 337): 158,99 176,99 176,76 158,76
I_HALL_P on Layer 2 "LAYER_2_I_HALL_P_P448" (solid, remove dead copper, pour order 448): 207,65 196,76 179,76 177,78 177,98 178,99 193,99 208,114 208,188 217,188 217,44 207,44
NetC1_1 on Layer 2 "LAYER_2_NETC1_1_P440" (solid, remove dead copper, pour order 440): 203,168 190,168 190,267 204,267 204,251 215,240 227,240 233,234 250,217 250,197 237,197 207,197 203,193
NetC1_2 on Layer 2 "LAYER_2_NETC1_2_P394" (solid, remove dead copper, pour order 394): 161,267 172,278 229,278 229,273 177,273 170,266 170,174 176,168 176,118 175,117 131,117 127,113 118,113 117,114 117,120 121,124 160,124 167,131 167,162 161,168
DC_POS on Layer 2 "Layer 1-DC_BUS_POS" (solid, remove dead copper, pour order 351): 152,157 156,161 156,264 152,268 142,278 49,278 39,268 0,268 0,230 27,230 30,227 30,197 49,178 55,178 63,170 101,170 116,155 116,146 109,139 92,139 63,110 63,77 68,72 68,58 76,50 100,50 100,82 80,82 74,88 74,100 81,107 100,107 100,119 102,121 114,121 121,128 156,128 161,133 161,145 154,145 152,147
GND on Layer 2 "Layer 2-GND" (solid, remove dead copper, pour order 429): 1,97 8,97 10,95 10,89 8,87 1,87 1,0 63.591,0 64.102,0.512 249.589,0.512 249.589,24.411 246.781,27.219 199.854,27.219 199.854,62.971 194.503,68.322 171.667,68.322 171.667,67.526 158.774,54.632 141,54.632 141,53 132.052,44.052 65,44.052 65,72 60,77 60,111 91,142 108,142 112,146 112,152.53 108.53,156 79,156 59,136 11,136 7,140 7,164 21,178 21,201 17,205 17,208 5,208 5,203 10,203 16,197 16,179 1,164
I_SW_NEG on Layer 2 "LAYER_2_I_SW_NEG_P348" (solid, remove dead copper, pour order 348): 142,63 160,63 163,66 163,72 147,72 142,67
I_SW_NEG on Layer 2 "LAYER_2_I_SW_NEG_P249" (solid, remove dead copper, pour order 249): 142,63 160,63 163,66 163,72 147,72 142,67
DC_DAB on Layer 2 "LAYER_2_DC_DAB_P252" (solid, remove dead copper, pour order 252): 23,143 23,152 28,157 39,157 46,150 59,150 59,143
DC_DAB on Layer 2 "LAYER_2_DC_DAB_P382" (solid, remove dead copper, pour order 382): 36,180 42,180 42,174 53,174 60,167 103,167 104,166 104,162 66,162 62,158 62,157 42,157 36,163
NetC2_1 on Layer 2 "LAYER_2_NETC2_1_P374" (solid, remove dead copper, pour order 374): 232,129.134 236,133.134 236,142 232,146 232,186 249,186 249,44 232,44
NetD15_1 on Layer 2 "LAYER_2_NETD15_1_P228" (solid, remove dead copper, pour order 228): 122,64 136,64 145,73 153,73 153,99 143,99 143,82 137,76 118,76 116,74 116,70
I_HALL_N on Layer 2 "LAYER_2_I_HALL_N_P271" (solid, remove dead copper, pour order 271): 158,99 176,99 176,76 158,76
DC_DAB on Layer 2 "LAYER_2_DC_DAB_P276" (solid, remove dead copper, pour order 276): 111,113.5 115,109.5 115,82.5 108.5,76 103,76 103,89.5 106,92.5 106,98.5 103,101.5 103,113.5

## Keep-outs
Keep-Out Layer:
  text ".Layer_Name" at 4.156,-42.206 h1.52

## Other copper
Top Layer:
  pour cut-out: 28,227 28,213 41,213 41,227
  pour cut-out: 98,144 98,154 113,154 113,144
  text ".Layer_Name" at 4.156,-42.206 h1.52
Layer 1:
  pour cut-out: 104,89 100,89 98,87 98,68 95,65 88,65 84,69 84,78 73,89 73,99 86,112 86,122 96,122 96,101 98,99 105,99 106,98 106,91
  pour cut-out: 98,144 98,154 113,154 113,144
Layer 2:
  pour cut-out: 28,227 28,213 41,213 41,227
  pour cut-out: 155,116 155,105 165,105 165,116
Bottom Layer:
  pour cut-out: 181.483,75 181.195,75 181.195,79 181.483,79
  pour cut-out: 171.517,79 171.805,79 171.805,76 171.517,76
  text ".Layer_Name" at 4.156,-42.206 h1.52

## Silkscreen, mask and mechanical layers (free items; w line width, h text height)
Top Overlay:
  circle w0.254: c164,32 r1.03
  circle w0.254: c14,32 r1.03
  circle w0.254: c14,157 r1.03
  circle w0.254: c164,157 r1.03
  circle w0.254: c79,94.5 r4
  circle w0.254: c132,94.5 r4
  text "Danger High Temperature" at 15.7,261.3 h3 r270
  text "Danger High Voltage" at 22.7,261.3 h3 r270
  text "'.PRJ_Number'-.PCB_Rev" at 66,129 h7
  text "12V" at 199.1,38.1 h0.7
  text "12V" at 199.145,21.57 h0.7
  text "TXD1" at 174.3,15.3 h1
  text "RXD1" at 187.3,15.3 h1
  text "TXD0" at 200.3,15.3 h1
  text "RXD0" at 214.3,15.3 h1
  text "TCLK" at 227.3,15.3 h1
  text "RCLK" at 240.3,15.3 h1
  text "GND" at 85.448,5.1 h0.8 r270
  text "GPIO4" at 86.942,5.1 h0.8 r270
  text "GPIO3" at 88.436,5.1 h0.8 r270
  text "GPIO2" at 89.931,5.1 h0.8 r270
  text "GPIO1" at 91.425,5.1 h0.8 r270
  text "PTE" at 92.92,5.1 h0.8 r270
  text "POCI" at 94.414,5.1 h0.8 r270
  text "PICO" at 95.909,5.1 h0.8 r270
  text "SCLK" at 97.403,5.1 h0.8 r270
  text "3V3" at 98.897,5.1 h0.8 r270
  text ".Layer_Name" at 4.156,-42.206 h1.52
Bottom Overlay:
  text "GND" at 236.3,268.7 h3
  text "DC_POS" at 209.3,265.2 h3
  text "Danger High Temperature" at 183.3,264.7 h3
  text "DC_POS" at 30.3,253.2 h3
  text "Danger High Voltage" at 176.3,246.7 h3
  text "'.PRJ_Number'-.PCB_Rev" at 94,238 h7
  text "1500 VDC, 33 A" at 44.3,228.7 h3
  text "DCAC_NEG" at 232.3,203.2 h3
  text "DC_NEG" at 26.3,194.2 h3
  text "DC_POS" at 19.3,160.033 h2
  text "DC_NEG" at 65.3,158.033 h2
  text "DC_BUS_POS" at 183.7,150.633 h2
  text "PWM3" at 118.7,149.3 h1
  text "PWM4" at 123.7,149.3 h1
  text "FLT3" at 128.7,149.3 h1
  text "FLT4" at 133.7,149.3 h1
  text "GND" at 137.7,149.3 h1
  text "12V" at 118.072,147.286 h1
  text "5V" at 123.072,147.286 h1
  text "RST" at 128.072,147.286 h1
  text "RDY" at 133.7,147.3 h1
  text "GND" at 137.7,147.3 h1
  text "G" at 117.7,97.3 h2
  text "KS" at 123.7,97.3 h2
  text "KS" at 89.7,96.3 h2
  text "G" at 93.7,96.3 h2
  text "KS" at 89.7,91.3 h2
  text "G" at 93.7,91.3 h2
  text "G" at 117.7,91.3 h2
  text "KS" at 123.7,91.3 h2
  text "DC_NEG" at 113.3,84.033 h2
  text "DC_POS" at 97.3,78.033 h2
  text "12V" at 12.7,71.3 h2
  text "12V" at 71.7,70.3 h2
  text "DCAC_POS" at 235.3,61.2 h3
  text "GND" at 71.7,59.3 h2
  text "GND" at 12.7,57.3 h2
  text "DC_NEG" at 77.033,54.7 h2 r270
  text "DC_POS" at 112.033,54.7 h2 r270
  text "GND" at 20.7,51.3 h2
  text "GND" at 96.7,47.3 h1
  text "RDY" at 101.7,47.3 h1
  text "RST" at 106.7,47.3 h1
  text "5V" at 111.7,47.3 h1
  text "12V" at 116.7,47.3 h1
  text "12V_Out" at 25.7,45.633 h2
  text "GND" at 96.7,45.3 h1
  text "FLT4" at 101.7,45.3 h1
  text "FLT3" at 106.7,45.3 h1
  text "PWM4" at 111.7,45.3 h1
  text "PWM3" at 116.7,45.3 h1
  text "3V3" at 60.7,28.3 h2
  text "GND" at 60.7,23.3 h2
  text "GND" at 159.7,17.3 h2
  text "GND" at 55.7,15.3 h2
  text "TXD1" at 175.341,7.709 h1
  text "RXD1" at 189.293,7.709 h1
  text "TXD0" at 203.978,7.709 h1
  text "RXD0" at 217.161,7.709 h1
  text "TCLK" at 230.784,7.709 h1
  text "RCLK" at 245.029,7.709 h1
  text "GND" at 59.65,5.028 h0.8 r270
  text "GPIO4" at 62.145,5.028 h0.8 r270
  text "GPIO3" at 64.639,5.028 h0.8 r270
  text "GPIO2" at 67.133,5.028 h0.8 r270
  text "GPIO1" at 69.628,5.028 h0.8 r270
  text "PTE" at 72.122,5.028 h0.8 r270
  text "POCI" at 74.617,5.028 h0.8 r270
  text "PICO" at 77.111,5.028 h0.8 r270
  text "SCLK" at 79.606,5.028 h0.8 r270
  text "3V3" at 82.1,5.028 h0.8 r270
  text ".Layer_Name" at 4.156,-42.206 h1.52
Top Paste:
  text ".Layer_Name" at 4.156,-42.206 h1.52
Bottom Paste:
  text ".Layer_Name" at 4.156,-42.206 h1.52
Top Solder:
  text ".Layer_Name" at 4.156,-42.206 h1.52
  text ".Layer_Name" at 4.156,-42.206 h1.52
Bottom Solder:
  text ".Layer_Name" at 4.156,-42.206 h1.52
Drill Guide:
  text ".Layer_Name" at 4.156,-42.206 h1.52
M1 Board Outline:
  lines w1: 0,0 0,280 250,280 250,0 0,0 ; 22,69.4 22,122.3 49,122.3 49,69.4 22,69.4
  text ".Layer_Name" at 4.156,-42.206 h1.52
M2 Board Dimensions:
  rectangle: -7.325,-30.56 2.2,-27.385
  rectangle: -10.5,-27.385 -7.325,-24.21
  lines w0.178: -10.5,-27.385 14.9,-27.385 ; -7.325,-30.56 -7.325,-24.21 ; -4.15,-30.56 -4.15,-24.21 ; 2.2,-30.56 2.2,-24.21 ; 8.55,-30.56 8.55,-24.21 ; -10.5,-30.56 -10.5,-24.21 14.9,-24.21 14.9,-30.56 -10.5,-30.56
  text ".Layer_Name" at 4.156,-42.206 h1.52
M3 3D STEP Top:
  text ".Layer_Name" at 4.156,-42.206 h1.52
M4 3D STEP Bottom:
  text ".Layer_Name" at 4.156,-42.206 h1.52
M5 Assembly Top:
  lines w0.254: -17.917,-44.026 149.723,-44.026 ; -17.917,-38.862 149.774,-38.862 ; -17.917,-33.697 -17.917,-49.191 83.81,-49.191 149.774,-49.191 149.774,-33.697 -17.904,-33.697 -17.904,-49.191 22.114,-49.191 ; 44.694,-49.191 44.694,-33.697 ; 76.876,-38.862 76.876,-33.697 ; 98.212,-38.862 98.212,-33.697 ; 114.011,-49.356 114.011,-44.204
  text "COMPONENTS MARKED 'DNP' SHOULD NOT BE POPULATED." at 18.799,-28.49 h1.52
  text "ASSEMBLY VARIANT:" at 18.786,-31.424 h1.52
  text ".VariantName" at 45.101,-31.424 h1.52
  text "PCB VIEWED FROM TOP SIDE" at -16.304,-37.054 h1.52
  text "BOARD #:" at 46.599,-37.054 h1.52
  text ".PRJ_Number" at 60.455,-37.054 h1.52
  text "REV:" at 81.905,-37.054 h1.52
  text ".PCB_Rev" at 89.309,-37.054 h1.52
  text "SVN REV:" at 103.19,-37.054 h1.52
  text ".VersionControl_RevNumber" at 116.043,-37.054 h1.52
  text "PLOT NAME =" at -16.304,-47.434 h1.52
  text ".plot_File_Name" at 4.156,-47.434 h1.52
  text "GENERATED    :" at 46.65,-47.434 h1.52
  text ".Print_Date" at 68.735,-47.434 h1.52
  text ".Print_Time" at 87.252,-47.434 h1.52
  text "TEXAS INSTRUMENTS" at 119.37,-47.434 h1.52
M6 Assembly Bottom:
  lines w0.254: -17.929,-38.874 149.761,-38.874 ; -17.879,-44.039 149.761,-44.039 ; 17.834,-49.369 17.834,-44.217 ; 33.633,-38.874 33.633,-33.71 ; 54.969,-38.874 54.969,-33.71 ; 87.15,-49.204 87.15,-33.71 ; 109.731,-49.204 149.749,-49.204 149.749,-33.71 -17.929,-33.71 -17.929,-49.204 48.034,-49.204 149.761,-49.204 149.761,-33.71
  text "COMPONENTS MARKED 'DNP' SHOULD NOT BE POPULATED." at 144.491,-28.477 h1.52
  text ".VariantName" at 117.973,-31.424 h1.52
  text "ASSEMBLY VARIANT:" at 144.364,-31.424 h1.52
  text ".VersionControl_RevNumber" at 15.802,-37.067 h1.52
  text "SVN REV:" at 28.654,-37.067 h1.52
  text ".PCB_Rev" at 42.535,-37.067 h1.52
  text "REV:" at 49.939,-37.067 h1.52
  text ".PRJ_Number" at 71.39,-37.067 h1.52
  text "BOARD #:" at 85.245,-37.067 h1.52
  text "PCB VIEWED FROM BOTTOM SIDE" at 148.148,-37.067 h1.52
  text "TEXAS INSTRUMENTS" at 12.474,-47.447 h1.52
  text ".Print_Time" at 44.593,-47.447 h1.52
  text ".Print_Date" at 63.109,-47.447 h1.52
  text "GENERATED    :" at 85.195,-47.447 h1.52
  text ".plot_File_Name" at 127.689,-47.447 h1.52
  text "PLOT NAME =" at 148.148,-47.447 h1.52
M9 Title Sheet:
  drawing of 63 lines, arcs and shapes, not listed
  text "1" at 24.793,446.35 h1.78
  text "2" at 126.266,446.35 h1.78
  text "3" at 227.739,446.35 h1.78
  text "4" at 329.365,446.35 h1.78
  text "5" at 430.923,446.35 h1.78
  text "6" at 532.48,446.35 h1.78
  text "7" at 634.123,446.35 h1.78
  text "8" at 735.596,446.35 h1.78
  text "A" at -22.374,385.441 h1.78
  text "A" at 782.806,385.441 h1.78
  text "B" at -22.374,258.441 h1.78
  text "B" at 782.806,258.441 h1.78
  text "C" at -22.374,131.441 h1.78
  text "C" at 782.806,131.441 h1.78
  text "D" at -22.374,4.441 h1.78
  text "D" at 782.806,4.441 h1.78
  text "PROJECT TITLE:" at 704.447,-13.577 h1.14
  text ".PRJ_Title" at 705.717,-16.964 h1.78
  text "DESIGNED FOR:" at 704.447,-21.223 h1.14
  text ".PRJ_Customer" at 705.717,-24.779 h1.78
  text "FILE NAME:" at 704.447,-28.843 h1.14
  text ".PCB_File_Name_No_Path" at 705.717,-31.891 h1.78
  text "Texas Instruments (TI) and/or its licensors do not warrant the accuracy or completeness of this specification" at 578.221,-36.001 h1.14
  text "ENGINEER:" at 704.447,-36.209 h1.14
  text "LAYOUT BY:" at 742.674,-36.209 h1.14
  text "or any information contained therein. TI and/or its licensors do not warrant that this design will meet" at 577.079,-38.863 h1.14
  text ".PRJ_Engineer" at 705.717,-40.146 h1.78
  text ".PCB_Layout" at 743.956,-40.146 h1.78
  text "the specifications, will be suitable for your application or fit for any particular purpose, or will operate in" at 577.079,-41.725 h1.14
  text ".Layer_Name" at 4.156,-42.206 h1.52
  text "ALTIUM DESIGNER VERSION:" at 742.674,-44.083 h1.14
  text "an implementation. TI and/or its licensors do not warrant that the design is production worthy. You should" at 577.079,-44.587 h1.14
  text "completely validate and test your design implementation to confirm the system functionality for your application." at 578.221,-47.448 h1.14
  text ".print_Scale" at 705.717,-47.469 h1.78
  text ".Application_BuildNumber" at 743.956,-47.469 h1.78
  text "1" at 24.793,-53.903 h1.78
  text "2" at 126.266,-53.903 h1.78
  text "3" at 227.739,-53.903 h1.78
  text "4" at 329.365,-53.903 h1.78
  text "5" at 430.923,-53.903 h1.78
  text "6" at 532.48,-53.903 h1.78
  text "7" at 634.123,-53.903 h1.78
  text "8" at 735.596,-53.903 h1.78
M10 Fab Notes:
  drawing of 189 lines, arcs and shapes, not listed
  text "DESIGN INFORMATION" at 730.876,141.275 h1.52
  text "MIN. TRACK WIDTH:" at 714.504,137.919 h1.52
  text "8" at 742.348,137.919 h1.52
  text "MIL" at 746.279,137.919 h1.52
  text "MIN. CLEARANCE:" at 714.504,134.767 h1.52
  text "7.874" at 738,134.767 h1.52
  text "MIL" at 746.279,134.767 h1.52
  text "MIN. VIA PAD SIZE:" at 714.504,131.614 h1.52
  text "24" at 741.587,131.614 h1.52
  text "MIL" at 746.279,131.614 h1.52
  text "0.05mm (2MIL)" at 732.157,128.314 h1.52
  text "MINIMUM ANNULAR RING" at 706.141,128.106 h1.52
  text "EXTERNAL" at 750.14,128.106 h1.52
  text "PER" at 711.221,125.308 h1.52
  text "IPC-D-275 CLASS 2 LEVEL C" at 716.809,125.308 h1.52
  text "MIL, HOLES" at 754.61,122.756 h1.52
  text "+/-" at 744.642,122.538 h1.52
  text "+/-" at 766.334,122.538 h1.52
  text "REGISTRATION TOLERANCES:" at 706.141,122.511 h1.52
  text "METAL" at 736.616,122.511 h1.52
  text "5" at 751.251,122.511 h1.52
  text "3" at 772.409,122.511 h1.52
  text "MIL" at 775.362,122.511 h1.52
  text "HOLE SIZE TOLERANCE (UNLESS OTHERWISE SPECIFIED):" at 706.141,120.014 h1.52
  text "+/-" at 766.334,119.941 h1.52
  text "3" at 772.409,119.914 h1.52
  text "MIL" at 775.362,119.914 h1.52
  text "MATERIAL:" at 704.242,116.418 h1.52
  text "FR-4 High Tg" at 729.298,113.153 h1.52
  text "X" at 725.629,112.95 h1.52
  text "FR-4" at 714.936,112.835 h1.52
  text "OTHER" at 752.731,112.835 h1.52
  text "(2.5mm)" at 723.066,109.202 h1.52
  text "X" at 720.016,109.14 h1.52
  text "THICKNESS:" at 706.141,108.994 h1.52
  text "OTHER" at 755.703,108.994 h1.52
  text "TOLERANCE:" at 706.141,105.48 h1.52
  text "X" at 727.687,105.48 h1.52
  text "ANSI IPC-6012 TYPE 3 CLASS 2" at 732.208,105.48 h1.52
  text "OTHER +/-" at 732.208,101.818 h1.52
  text "BOW & TWIST:" at 706.141,98.13 h1.52
  text "X" at 727.687,98.13 h1.52
  text "ANSI IPC-6012 TYPE 3 CLASS 2" at 732.208,98.13 h1.52
  text "OTHER +/-" at 732.208,94.404 h1.52
  text "DRILLING:" at 704.242,91.086 h1.52
  text "NC_DRILL FILES" at 748.972,88.415 h1.52
  text "REFERENCE:" at 706.141,88.315 h1.52
  text "X" at 722.835,88.312 h1.52
  text "AS SHOWN" at 727.356,88.315 h1.52
  text "X" at 745.721,88.315 h1.52
  text "OTHER" at 756.541,84.701 h1.52
  text "PTH COPPER THICKNESS:" at 706.133,84.612 h1.52
  text "X" at 735.07,84.612 h1.52
  text "3OZ" at 738.321,84.612 h1.52
  text "BOARD FINISH:" at 704.242,80.863 h1.52
  text "SILKSCREEN:" at 708.185,78.066 h1.52
  text "X" at 732.513,78.066 h1.52
  text "TOP" at 735.484,78.066 h1.52
  text "X" at 745.467,78.066 h1.52
  text "BOTTOM" at 748.464,78.066 h1.52
  text "SILKSCREEN COLOR:" at 708.185,74.124 h1.52
  text "X" at 732.487,74.124 h1.52
  text "WHITE" at 735.484,74.124 h1.52
  text "OTHER" at 748.464,74.124 h1.52
  text "X" at 735.815,70.48 h1.52
  text "GREEN" at 738.812,70.48 h1.52
  text "OTHER" at 754.509,70.48 h1.52
  text "SOLDER RESIST COLOR:" at 708.185,70.306 h1.52
  text "X" at 735.815,66.562 h1.52
  text "MATTE" at 738.812,66.562 h1.52
  text "SEMI-GLOSS" at 754.497,66.546 h1.52
  text "IMMERSION GOLD (ENIG)" at 731.192,62.174 h1.52
  text "ENEPIG" at 765.165,61.99 h1.52
  text "SURFACE FINISH:" at 704.242,61.965 h1.52
  text "X" at 726.671,61.965 h1.52
  text "IMM. TIN/SILVER OR EQUIV" at 712.613,58.477 h1.52
  text "OTHER" at 748.972,58.377 h1.52
  text "ARRAY/PANEL:" at 704.242,54.431 h1.52
  text "CUT AND TRIM PER M1 BOARD OUTLINE" at 731.192,54.222 h1.52
  text "N.C. ROUTE" at 731.192,50.768 h1.52
  text "X" at 748.667,50.768 h1.52
  text "V. SCORE" at 753.188,50.768 h1.52
  text "CERTIFICATION:" at 704.242,47.488 h1.52
  text "MATERIALS AND WORKMANSHIP FOR ALL PCBS" at 722.657,47.488 h1.52
  text "TO MEET OR EXCEED THE REQUIREMENTS OF:" at 722.657,45.099 h1.52
  text "X" at 713.45,41.832 h1.52
  text "ANSI IPC-A-600F CLASS ->" at 716.701,41.832 h1.52
  text "X" at 758.56,41.832 h1.52
  text "2" at 761.354,41.832 h1.52
  text "1" at 753.353,41.794 h1.52
  text "3" at 770.346,41.794 h1.52
  text "X" at 734.075,38.081 h1.52
  text "RoHS" at 737.326,38.081 h1.52
  text "OTHER" at 753.694,38.081 h1.52
  text "PER ORDER" at 763.779,38.081 h1.52
  text "ALL BOARDS MUST MEET OR EXCEED UL94-V0 REQUIREMENTS." at 704.942,34.174 h1.52
  text "PCB MUST BEAR THE UL94V-0 UL REGISTERED MATERIAL ID NUMBER" at 704.942,31.226 h1.52
  text "ADDITIONAL REQUIREMENTS:" at 704.242,26.922 h1.52
  text "MICROSECTION:" at 706.141,24.201 h1.52
  text "YES" at 729.147,24.201 h1.52
  text "REQUIRED" at 751.029,20.535 h1.52
  text "BARE BOARD ELEC. TEST:" at 706.141,20.463 h1.52
  text "NONE" at 739.307,20.463 h1.52
  text "X" at 748.032,20.463 h1.52
  text "PER ORDER" at 766.066,20.463 h1.52
  text "XX MIL VIAS REQUIRE NON-CONDUCTIVE FILL AND PLANARIZE" at 710.412,15.257 h1.5
  text "XX MIL VIAS REQUIRE CONDUCTIVE FILL AND PLANARIZE" at 710.616,12.616 h1.52
  text "OUTER XX MIL TRACES REQUIRE 50 OHM SINGLE-ENDED IMPEDANCE" at 710.591,8.466 h1.47
  text "LAYER 2 & 3 (INNER LAYERS) XX MIL WIDE, XX MIL SPACE / TRACES REQUIRE 100 OHM DIFFERENTIAL IMPEDANCE" at 710.387,2.479 h1.52
  text ".Layer_Name" at 4.156,-42.206 h1.52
